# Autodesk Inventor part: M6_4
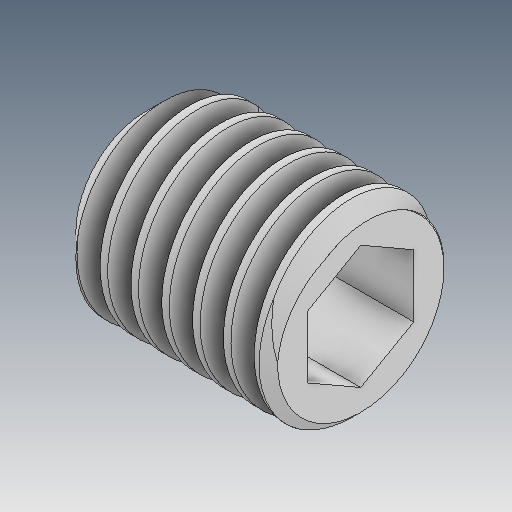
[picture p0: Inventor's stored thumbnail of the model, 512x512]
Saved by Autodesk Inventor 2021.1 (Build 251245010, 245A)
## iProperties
Created: 2019-04
Part Number: M6_4
Material: Ogólny
Document SubType Name: Modeling
Designer: user
Density: 1 g/cm^3
Appearance: Domyślna
Author: user
Revision Number: ÈÎºÎ
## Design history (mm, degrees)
feature "ÊäÈë1"
node "Bryła1"
